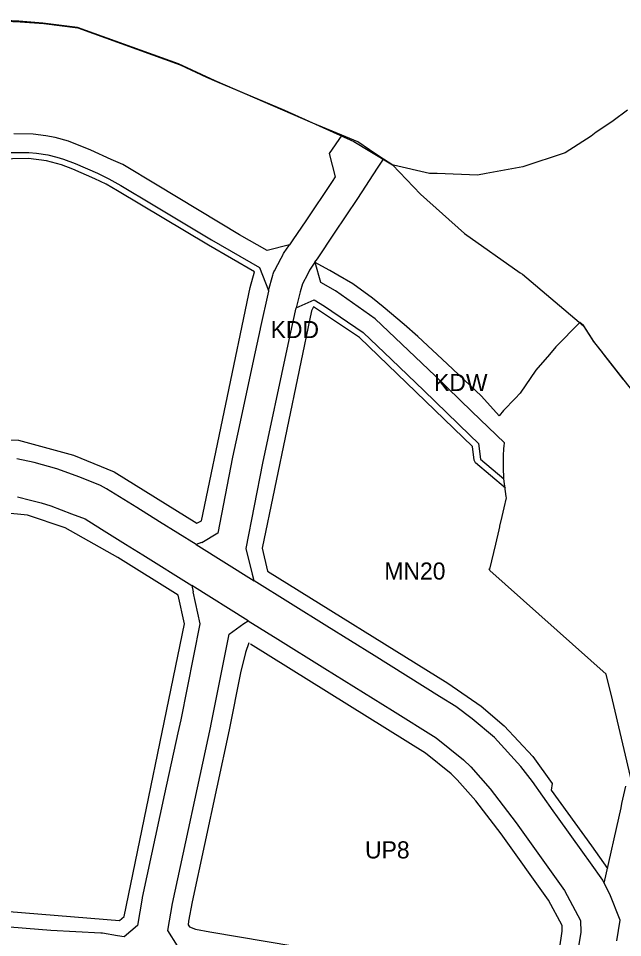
# Model space of a CAD drawing. Extents: x 7428103 to 7431580, y 5545880 to 5549002.
# Drawn here: x 7430729.6 to 7430925.4, y 5547441.7 to 5547739.8 of the extents above; entities that cross this region are included whole.
import ezdxf

# ---------------------------------------------------------------- set-up
doc = ezdxf.new("R2010")
doc.units = 0
for name, color, linetype in [('CZ_L_linie rozgraniczające tereny o różnym przeznaczeniu oraz różnych warunkach ich zabudowy i zagospodarowania', 7, 'Continuous'), ('CZ_L_maksymalne nieprzekraczalne linie zabudowy', 7, 'Continuous'), ('CZ_L_opisy_linie rozgraniczające tereny o różnym przeznaczeniu oraz różnych warunkach ich zabudowy i zagospodarowania', 7, 'Continuous'), ('Łąki_Nowohuckie', 7, 'Continuous')]:
    doc.layers.add(name, color=color, linetype=linetype)

msp = doc.modelspace()

# ---------------------------------------------------------------- linework, layer by layer
at = {"layer": 'CZ_L_linie rozgraniczające tereny o różnym przeznaczeniu oraz różnych warunkach ich zabudowy i zagospodarowania'}
for p, q in [((7430729.73, 5547738.83), (7430708.44, 5547739.76)), ((7430737.45, 5547738.17), (7430729.73, 5547738.83)), ((7430748.78, 5547736.77), (7430737.45, 5547738.17)), ((7430781.41, 5547725.02), (7430748.78, 5547736.77)), ((7430793.36, 5547719.53), (7430781.41, 5547725.02)), ((7430825.02, 5547705.84), (7430793.36, 5547719.53)), ((7430927.02, 5547710), (7430922.34, 5547706.55)), ((7430834.43, 5547701.88), (7430825.02, 5547705.84)), ((7430918.68, 5547704.09), (7430916.85, 5547702.86)), ((7430922.34, 5547706.55), (7430918.68, 5547704.09)), ((7430734.35, 5547702.22), (7430728.1, 5547702.36)), ((7430738.51, 5547701.68), (7430734.35, 5547702.22)), ((7430741.5, 5547701.1), (7430738.51, 5547701.68)), ((7430745.84, 5547699.95), (7430741.5, 5547701.1)), ((7430834.43, 5547701.88), (7430830.29, 5547695.93)), ((7430839.61, 5547699.7), (7430834.43, 5547701.88)), ((7430915.14, 5547701.62), (7430906.73, 5547696.19)), ((7430916.85, 5547702.86), (7430915.14, 5547701.62)), ((7430753.07, 5547697.04), (7430745.84, 5547699.95)), ((7430843.36, 5547697.14), (7430839.61, 5547699.7)), ((7430726.23, 5547696.23), (7430733.01, 5547696.31)), ((7430733.01, 5547696.31), (7430735.43, 5547696.03)), ((7430735.43, 5547696.03), (7430739.1, 5547695.5)), ((7430739.1, 5547695.5), (7430742.02, 5547694.75)), ((7430742.02, 5547694.75), (7430744.16, 5547694.17)), ((7430759.67, 5547694.03), (7430753.07, 5547697.04)), ((7430830.29, 5547695.93), (7430832.2, 5547688.37)), ((7430847.84, 5547694.08), (7430843.36, 5547697.14)), ((7430906.73, 5547696.19), (7430893.07, 5547691.66)), ((7430744.16, 5547694.17), (7430747.93, 5547692.68)), ((7430747.93, 5547692.68), (7430755.18, 5547689.56)), ((7430763.41, 5547692.39), (7430759.67, 5547694.03)), ((7430774.54, 5547685.65), (7430763.41, 5547692.39)), ((7430845.99, 5547691.22), (7430847.69, 5547693.83)), ((7430847.69, 5547693.83), (7430847.76, 5547693.95)), ((7430847.76, 5547693.95), (7430847.84, 5547694.08)), ((7430850.92, 5547692.22), (7430847.84, 5547694.08)), ((7430851.09, 5547692.18), (7430850.92, 5547692.22)), ((7430862.83, 5547689.49), (7430851.09, 5547692.18)), ((7430755.18, 5547689.56), (7430758.91, 5547687.79)), ((7430839.59, 5547681.38), (7430845.99, 5547691.22)), ((7430865.29, 5547689.42), (7430862.83, 5547689.49)), ((7430878.33, 5547688.95), (7430865.29, 5547689.42)), ((7430881.13, 5547689.47), (7430878.33, 5547688.95)), ((7430893.07, 5547691.66), (7430881.13, 5547689.47)), ((7430758.91, 5547687.79), (7430762.75, 5547685.63)), ((7430831.23, 5547686.87), (7430822.68, 5547674.16)), ((7430832.2, 5547688.37), (7430831.23, 5547686.87)), ((7430762.75, 5547685.63), (7430773.3, 5547679.32)), ((7430801.19, 5547669.63), (7430774.54, 5547685.65)), ((7430832.05, 5547670.17), (7430839.55, 5547681.32)), ((7430839.55, 5547681.32), (7430839.59, 5547681.38)), ((7430773.3, 5547679.32), (7430792.19, 5547667.97)), ((7430822.68, 5547674.16), (7430818.49, 5547667.92)), ((7430792.19, 5547667.97), (7430807.71, 5547658.97)), ((7430810.21, 5547664.55), (7430801.19, 5547669.63)), ((7430818.49, 5547667.92), (7430817.42, 5547666.33)), ((7430826.46, 5547661.85), (7430832.05, 5547670.17)), ((7430817.42, 5547666.33), (7430810.21, 5547664.55)), ((7430815.74, 5547663.83), (7430817.24, 5547666.05)), ((7430817.24, 5547666.05), (7430817.42, 5547666.33)), ((7430812.54, 5547657.89), (7430814.7, 5547662.01)), ((7430814.7, 5547662.01), (7430815.24, 5547663.03)), ((7430815.24, 5547663.03), (7430815.4, 5547663.31)), ((7430815.4, 5547663.31), (7430815.51, 5547663.49)), ((7430815.51, 5547663.49), (7430815.74, 5547663.83)), ((7430807.71, 5547658.97), (7430810.63, 5547651.51)), ((7430825.67, 5547660.68), (7430824.37, 5547658.75)), ((7430825.69, 5547660.7), (7430825.67, 5547660.68)), ((7430825.69, 5547660.7), (7430826.46, 5547661.85)), ((7430825.7, 5547660.67), (7430825.69, 5547660.7)), ((7430827.63, 5547654.13), (7430825.7, 5547660.67)), ((7430830.25, 5547658.11), (7430825.7, 5547660.67)), ((7430810.64, 5547651.56), (7430812.03, 5547656.49)), ((7430812.03, 5547656.49), (7430812.15, 5547656.91)), ((7430812.15, 5547656.91), (7430812.16, 5547656.98)), ((7430812.16, 5547656.98), (7430812.27, 5547657.29)), ((7430812.27, 5547657.29), (7430812.39, 5547657.59)), ((7430812.39, 5547657.59), (7430812.53, 5547657.88)), ((7430812.53, 5547657.88), (7430812.54, 5547657.89)), ((7430823.22, 5547656.72), (7430821.63, 5547653.7)), ((7430823.96, 5547658.14), (7430823.22, 5547656.72)), ((7430824.37, 5547658.75), (7430823.96, 5547658.14)), ((7430830.5, 5547657.97), (7430830.25, 5547658.11)), ((7430833.14, 5547656.49), (7430830.5, 5547657.97)), ((7430837.95, 5547653.68), (7430833.14, 5547656.49)), ((7430821.63, 5547653.7), (7430820.91, 5547651.14)), ((7430832.32, 5547651.38), (7430827.63, 5547654.13)), ((7430844.29, 5547649.06), (7430837.95, 5547653.68)), ((7430810.58, 5547651.29), (7430807.89, 5547639.2)), ((7430810.63, 5547651.51), (7430810.58, 5547651.3)), ((7430810.58, 5547651.3), (7430810.58, 5547651.29)), ((7430810.63, 5547651.51), (7430810.64, 5547651.56)), ((7430820.91, 5547651.14), (7430820.31, 5547648.98)), ((7430845.22, 5547642.4), (7430832.32, 5547651.38)), ((7430820.31, 5547648.98), (7430819.63, 5547645.93)), ((7430819.63, 5547645.93), (7430825.41, 5547648.49)), ((7430825.41, 5547648.49), (7430828.78, 5547646.5)), ((7430847.79, 5547646.28), (7430844.29, 5547649.06)), ((7430817.66, 5547637.05), (7430819.63, 5547645.93)), ((7430828.78, 5547646.5), (7430841.35, 5547637.87)), ((7430854.62, 5547640.52), (7430847.79, 5547646.28)), ((7430864.64, 5547623.83), (7430845.22, 5547642.4)), ((7430911.56, 5547641.17), (7430903.76, 5547633.29)), ((7430912.72, 5547640.19), (7430911.56, 5547641.17)), ((7430807.88, 5547639.16), (7430805.74, 5547629.14)), ((7430807.89, 5547639.2), (7430807.88, 5547639.16)), ((7430859.02, 5547636.64), (7430854.62, 5547640.52)), ((7430914.84, 5547636.88), (7430912.72, 5547640.19)), ((7430814.95, 5547624.42), (7430817.66, 5547637.05)), ((7430841.35, 5547637.87), (7430850.47, 5547629.16)), ((7430868.58, 5547627.72), (7430859.02, 5547636.64)), ((7430915.98, 5547635.1), (7430914.84, 5547636.88)), ((7430903.76, 5547633.29), (7430901.69, 5547630.82)), ((7430918.93, 5547631.32), (7430915.98, 5547635.1)), ((7430850.47, 5547629.16), (7430860.93, 5547619.09)), ((7430901.69, 5547630.82), (7430897.21, 5547625.69)), ((7430919.13, 5547631.07), (7430918.93, 5547631.32)), ((7430925.59, 5547622.81), (7430919.13, 5547631.07)), ((7430805.74, 5547629.14), (7430801.09, 5547607.43)), ((7430879.64, 5547617.23), (7430868.58, 5547627.72)), ((7430810.51, 5547603.67), (7430814.95, 5547624.42)), ((7430876.49, 5547612.32), (7430864.64, 5547623.83)), ((7430897.21, 5547625.69), (7430892.14, 5547618.29)), ((7430860.93, 5547619.09), (7430875.85, 5547604.61)), ((7430892.14, 5547618.29), (7430890.6, 5547616.56)), ((7430885.42, 5547610.89), (7430879.64, 5547617.23)), ((7430890.6, 5547616.56), (7430886.83, 5547612.64)), ((7430887.12, 5547602.16), (7430876.49, 5547612.32)), ((7430886.83, 5547612.64), (7430885.42, 5547610.89)), ((7430801.09, 5547607.43), (7430798.98, 5547597.56)), ((7430808.76, 5547595.51), (7430810.51, 5547603.67)), ((7430875.85, 5547604.61), (7430878.67, 5547601.9)), ((7430878.67, 5547601.9), (7430879.29, 5547596.84)), ((7430886.83, 5547597.91), (7430886.89, 5547600.3)), ((7430886.89, 5547600.3), (7430886.99, 5547601.11)), ((7430886.99, 5547601.11), (7430887.12, 5547602.16)), ((7430734.68, 5547595.76), (7430729.05, 5547596.99)), ((7430798.96, 5547597.47), (7430795.38, 5547579.08)), ((7430798.98, 5547597.56), (7430798.96, 5547597.47)), ((7430879.29, 5547596.84), (7430886.86, 5547590.49)), ((7430886.76, 5547594.71), (7430886.83, 5547597.91)), ((7430742.03, 5547593.68), (7430734.68, 5547595.76)), ((7430749.46, 5547591.05), (7430742.03, 5547593.68)), ((7430803.41, 5547567.95), (7430808.76, 5547595.51)), ((7430886.75, 5547594.2), (7430886.76, 5547594.71)), ((7430886.79, 5547594.16), (7430886.75, 5547594.2)), ((7430886.85, 5547590.56), (7430886.79, 5547594.16)), ((7430756.18, 5547588.34), (7430749.46, 5547591.05)), ((7430886.86, 5547590.49), (7430886.85, 5547590.56)), ((7430887.68, 5547584.71), (7430886.86, 5547590.49)), ((7430758.13, 5547587.26), (7430756.18, 5547588.34)), ((7430729.3, 5547584.64), (7430733.54, 5547583.61)), ((7430767.99, 5547581.16), (7430758.13, 5547587.26)), ((7430887.74, 5547584.37), (7430887.68, 5547584.71)), ((7430733.54, 5547583.61), (7430736.97, 5547582.7)), ((7430736.97, 5547582.7), (7430740.07, 5547581.7)), ((7430740.07, 5547581.7), (7430746.8, 5547579.18)), ((7430886.99, 5547581.06), (7430887.74, 5547584.36)), ((7430887.74, 5547584.36), (7430887.74, 5547584.37)), ((7430746.8, 5547579.18), (7430751.25, 5547577.55)), ((7430775.29, 5547576.56), (7430767.99, 5547581.16)), ((7430795.38, 5547579.08), (7430794.18, 5547572.89)), ((7430886.35, 5547578.28), (7430886.99, 5547581.06)), ((7430751.25, 5547577.55), (7430756.55, 5547574.2)), ((7430787.14, 5547569.17), (7430775.29, 5547576.56)), ((7430885.64, 5547575.16), (7430886.35, 5547578.28)), ((7430756.55, 5547574.2), (7430764.31, 5547569.3)), ((7430794.18, 5547572.89), (7430789.02, 5547569.76)), ((7430884.28, 5547569.29), (7430885.35, 5547573.96)), ((7430885.35, 5547573.96), (7430885.57, 5547574.94)), ((7430885.57, 5547574.94), (7430885.59, 5547574.95)), ((7430885.59, 5547574.95), (7430885.64, 5547575.16)), ((7430788.91, 5547569.84), (7430787.14, 5547569.17)), ((7430789.02, 5547569.76), (7430788.91, 5547569.84)), ((7430764.31, 5547569.3), (7430769.86, 5547565.81)), ((7430787.14, 5547569.17), (7430805.98, 5547557.42)), ((7430805.43, 5547559.54), (7430803.41, 5547567.95)), ((7430882.32, 5547561.19), (7430884.28, 5547569.29)), ((7430769.86, 5547565.81), (7430785.79, 5547555.87)), ((7430882.36, 5547560.78), (7430882.17, 5547561.27)), ((7430882.17, 5547561.27), (7430882.32, 5547561.19)), ((7430920.08, 5547527.17), (7430882.36, 5547560.78)), ((7430805.46, 5547559.52), (7430805.43, 5547559.54)), ((7430805.98, 5547557.42), (7430805.46, 5547559.52)), ((7430804.08, 5547544.47), (7430785.79, 5547555.87)), ((7430785.79, 5547555.87), (7430786.19, 5547553.85)), ((7430829.49, 5547542.76), (7430805.98, 5547557.42)), ((7430786.19, 5547553.85), (7430786.15, 5547553.88)), ((7430786.15, 5547553.88), (7430788.39, 5547543.45)), ((7430788.39, 5547543.45), (7430782.17, 5547512.39)), ((7430797.92, 5547540.13), (7430802.63, 5547543.61)), ((7430802.63, 5547543.61), (7430802.67, 5547543.58)), ((7430802.67, 5547543.58), (7430804.08, 5547544.47)), ((7430804.08, 5547544.47), (7430813.7, 5547538.47)), ((7430844.89, 5547533.16), (7430829.49, 5547542.76)), ((7430791.97, 5547510.38), (7430797.92, 5547540.13)), ((7430813.7, 5547538.47), (7430828.91, 5547528.99)), ((7430866.06, 5547519.96), (7430844.89, 5547533.16)), ((7430828.91, 5547528.99), (7430850.76, 5547515.36)), ((7430922.07, 5547518.83), (7430920.08, 5547527.17)), ((7430871.38, 5547516.65), (7430866.06, 5547519.96)), ((7430876.63, 5547512.66), (7430871.38, 5547516.65)), ((7430928.41, 5547492.11), (7430922.07, 5547518.83)), ((7430850.76, 5547515.36), (7430865, 5547506.48)), ((7430779.49, 5547452.79), (7430791.95, 5547510.31)), ((7430782.17, 5547512.39), (7430781.24, 5547508.09)), ((7430791.95, 5547510.31), (7430791.97, 5547510.38)), ((7430883.82, 5547506.57), (7430876.63, 5547512.66)), ((7430781.24, 5547508.09), (7430776.97, 5547488.4)), ((7430865, 5547506.48), (7430873.78, 5547499.38)), ((7430892.4, 5547497.21), (7430883.82, 5547506.57)), ((7430873.78, 5547499.38), (7430876.16, 5547497.11)), ((7430876.16, 5547497.11), (7430882.44, 5547489.95)), ((7430896.15, 5547492.4), (7430892.4, 5547497.21)), ((7430902.87, 5547482.87), (7430896.15, 5547492.4)), ((7430882.44, 5547489.95), (7430890.85, 5547479.01)), ((7430925.17, 5547485.2), (7430926.44, 5547490.87)), ((7430776.97, 5547488.4), (7430769.69, 5547454.79)), ((7430919.44, 5547459.45), (7430924.86, 5547483.79)), ((7430924.86, 5547483.79), (7430925.17, 5547485.2)), ((7430904.26, 5547480.89), (7430902.87, 5547482.87)), ((7430912.51, 5547469.44), (7430904.26, 5547480.89)), ((7430890.85, 5547479.01), (7430906.5, 5547457.01)), ((7430914.96, 5547466.03), (7430912.51, 5547469.44)), ((7430918.98, 5547460.35), (7430914.96, 5547466.03)), ((7430919.44, 5547459.45), (7430918.98, 5547460.35)), ((7430921.29, 5547455.79), (7430919.44, 5547459.45)), ((7430906.5, 5547457.01), (7430911.7, 5547447.28)), ((7430769.64, 5547454.55), (7430768.16, 5547445.64)), ((7430769.69, 5547454.79), (7430769.64, 5547454.55)), ((7430924.59, 5547447.41), (7430921.29, 5547455.79)), ((7430778.02, 5547444.03), (7430779.49, 5547452.79)), ((7430923.49, 5547440.65), (7430924.59, 5547447.41)), ((7430740.06, 5547444.05), (7430714.93, 5547446.02)), ((7430768.16, 5547445.64), (7430763.83, 5547441.99)), ((7430911.7, 5547447.28), (7430911.79, 5547443.46)), ((7430756.33, 5547443.21), (7430740.06, 5547444.05)), ((7430756.46, 5547443.2), (7430756.33, 5547443.21)), ((7430756.78, 5547443.16), (7430756.46, 5547443.2)), ((7430756.83, 5547443.15), (7430756.78, 5547443.16)), ((7430761.65, 5547442.35), (7430756.83, 5547443.15)), ((7430763.83, 5547441.99), (7430761.65, 5547442.35)), ((7430781.17, 5547439.11), (7430778.02, 5547444.03)), ((7430911.79, 5547443.46), (7430910.38, 5547434.78))]:
    msp.add_line(p, q, dxfattribs=at)
at = {"layer": 'CZ_L_maksymalne nieprzekraczalne linie zabudowy'}
for points in [[(7430787.39, 5547576.09), (7430788.89, 5547576.88), (7430804.7, 5547652.52), (7430806.1, 5547657.59), (7430791.16, 5547666.25), (7430761.74, 5547683.9), (7430757.99, 5547686.01), (7430754.35, 5547687.74), (7430747.17, 5547690.83), (7430743.53, 5547692.27), (7430738.71, 5547693.54), (7430732.9, 5547694.31), (7430717.18, 5547694.05)], [(7430887.39, 5547587.41), (7430877.68, 5547595.65), (7430877.32, 5547596.5), (7430876.77, 5547600.95), (7430840.09, 5547636.31), (7430825.21, 5547646.22), (7430824.52, 5547644.91), (7430808.53, 5547568.04), (7430810.35, 5547560.59), (7430868.71, 5547524.2), (7430879.51, 5547516.75), (7430887.05, 5547510.38), (7430896.24, 5547500.41), (7430902.59, 5547491.66), (7430902.25, 5547489.57), (7430915.34, 5547471.5), (7430920.47, 5547464.1)], [(7430718.07, 5547603.39), (7430729.59, 5547602.97), (7430747.44, 5547598.12), (7430760.56, 5547592.74), (7430787.39, 5547576.09)], [(7430762.36, 5547447.29), (7430763.84, 5547448.54), (7430783.45, 5547543.43), (7430781.33, 5547552.76), (7430761.76, 5547565), (7430744.76, 5547574.59), (7430732.48, 5547578.69), (7430717.1, 5547580.27), (7430679.42, 5547578.62), (7430616.34, 5547573.27), (7430615.14, 5547573.32), (7430605.2, 5547574.95), (7430594.21, 5547576.42), (7430582.49, 5547574.81), (7430578.9, 5547571.26), (7430578.47, 5547567.46), (7430648.83, 5547467.19), (7430652.37, 5547455.77), (7430656.58, 5547451.53), (7430689.39, 5547453.26), (7430762.36, 5547447.29)], [(7430804.2, 5547537.31), (7430803.13, 5547534.19), (7430801.59, 5547527.59), (7430797.83, 5547509.09), (7430785.86, 5547453.37), (7430784.67, 5547447.03), (7430784.56, 5547445.94), (7430785.01, 5547445.21), (7430787.01, 5547444.52), (7430791.64, 5547443.59), (7430837.04, 5547435.92)], [(7430903, 5547424.51), (7430905.78, 5547443.88), (7430905.74, 5547445.71), (7430901.39, 5547453.84), (7430886.03, 5547475.44), (7430877.81, 5547486.14), (7430871.82, 5547492.95), (7430869.81, 5547494.87), (7430861.52, 5547501.58), (7430804.83, 5547536.93)]]:
    msp.add_lwpolyline(points, dxfattribs=at)
at = {"layer": 'Łąki_Nowohuckie'}
for p, q in [((7430790.55, 5547720.71), (7430793.78, 5547719.35)), ((7430793.78, 5547719.35), (7430815.78, 5547710.04)), ((7430815.78, 5547710.04), (7430838.32, 5547699.88)), ((7430838.32, 5547699.88), (7430843.47, 5547696.75)), ((7430843.47, 5547696.75), (7430850.78, 5547692.26)), ((7430850.78, 5547692.26), (7430859.9, 5547682.78)), ((7430859.9, 5547682.78), (7430874.14, 5547669.97)), ((7430874.14, 5547669.97), (7430892.17, 5547657.31))]:
    msp.add_line(p, q, dxfattribs=at)
for points in [[(7430708.72, 5547739.64), (7430730.13, 5547738.64), (7430737.78, 5547738.09)], [(7430737.78, 5547738.09), (7430748.89, 5547736.65), (7430781.95, 5547724.69), (7430790.55, 5547720.71)], [(7430892.17, 5547657.31), (7430892.92, 5547656.79), (7430912.74, 5547640.09)], [(7430912.74, 5547640.09), (7430916, 5547635), (7430929.34, 5547617.94), (7430930.48, 5547616.55)]]:
    msp.add_lwpolyline(points, dxfattribs=at)

# ---------------------------------------------------------------- texts
at = {"layer": 'CZ_L_opisy_linie rozgraniczające tereny o różnym przeznaczeniu oraz różnych warunkach ich zabudowy i zagospodarowania'}
for s, p in [('KDD', (7430811.33, 5547636.11)), ('KDW', (7430864.3, 5547618.94)), ('MN20', (7430848.18, 5547557.81)), ('UP8', (7430841.92, 5547467.42))]:
    msp.add_text(s, height=5.549, dxfattribs=at).set_placement(p)

doc.saveas('drawing.dxf')
